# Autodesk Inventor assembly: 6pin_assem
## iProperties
Shininess: 64.0
Length Units: 11272
Angle Units: 11279
Time Units: 11290
Mass Units: 11286
Length Display Precision: 3
Angle Display Precision: 2
Compacted: True
Part Number: 6pin_assem
Document SubType Name: Assembly
Created: 2007-10
Designer: jpalmisano
Manufacturer: Standard
Standards Organization: Custom
Density: 0.0
Volumn: 0.0
Area: 0.0
PropertySet Name: Model Information
Control State: 0
Master: False
Checked Out: False
Author: jpalmisano
